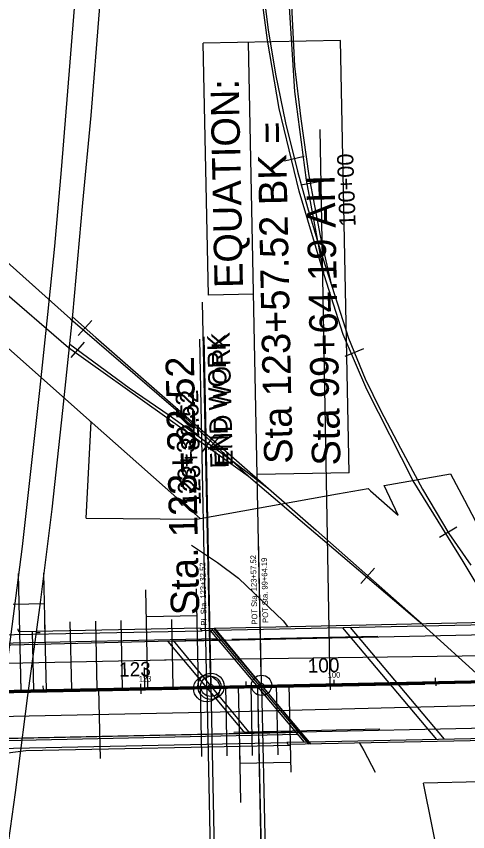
# Model space of a CAD drawing. Extents: x -25029 to 2274964, y -81170 to 687028.
# Drawn here: x -4749.3 to -4526.9, y -66503.3 to -66101.5 of the extents above; entities that cross this region are included whole.
import ezdxf

# ---------------------------------------------------------------- set-up
doc = ezdxf.new("R2010")
doc.units = 0
for name, color, linetype in [('81911BEA - RW_X_Fee_RW', 7, 'Continuous'), ('AP_X_Runway', 7, 'Continuous'), ('BD_X_Canopy', 7, 'Continuous'), ('BR_X_Rail_Object', 7, 'Continuous'), ('Default', 7, 'Continuous'), ('GE_X_CL_100', 7, 'Continuous'), ('GE_X_CL_20', 7, 'Continuous'), ('GK_Visualization', 7, 'Continuous'), ('MT_P_Lane_Line', 7, 'Continuous'), ('PM_P_CL_Double_Solid', 7, 'Continuous'), ('PM_P_Stop_Line', 7, 'Continuous'), ('PV_X_Curb', 7, 'Continuous'), ('PV_X_EOP', 7, 'Continuous'), ('RD_P_Gate', 7, 'Continuous'), ('RD_X_Bumper_Block', 7, 'Continuous'), ('RD_X_GR_Rt', 7, 'Continuous'), ('RD_X_RR_1', 7, 'Continuous'), ('RR', 7, 'Continuous'), ('WALL', 7, 'Continuous')]:
    doc.layers.add(name, color=color, linetype=linetype)

msp = doc.modelspace()

# ---------------------------------------------------------------- linework, layer by layer
at = {"layer": '81911BEA - RW_X_Fee_RW'}
for q in [(-4712.38, -66301.35), (-4660.28, -66349.23)]:
    msp.add_line((-4714.87, -66348.84), q, dxfattribs=at)
for points in [[(-4864.04, -66166.72), (-4711.93, -66301.75), (-4658.75, -66348.95)], [(-4660.28, -66349.23), (-4658.75, -66348.95), (-4591.13, -66336.87), (-4575.99, -66334.17), (-4574.86, -66335.35), (-4561.13, -66347.36), (-4568.02, -66332.74), (-4535.39, -66326.91), (-4528.57, -66339.93), (-4523.13, -66350.33), (-4512.37, -66368.29), (-4506.47, -66378.13), (-4505.97, -66379.3), (-4505.54, -66378.96), (-4505.01, -66378.54), (-4504.45, -66378.09), (-4412.16, -66304.9), (-4388.93, -66286.47), (-4356.73, -66260.93), (-4338.07, -66246.14), (-4326.25, -66236.76), (-4315.27, -66287.59)], [(-4044.67, -66469.26), (-4258.38, -66473.52), (-4520.55, -66478.74), (-4548.73, -66479.3)], [(-4366.67, -67383.31), (-4370, -67366.77), (-4388.22, -67276.31), (-4407.96, -67178.28), (-4459.99, -66919.94), (-4518.67, -66628.59), (-4548.73, -66479.3)]]:
    msp.add_lwpolyline(points, dxfattribs=at)
at = {"layer": 'AP_X_Runway'}
for p, q in [((-3221.39, -66402.05), (-5080.45, -66441.35)), ((-4643.08, -66408.46), (-4571.24, -66406.89)), ((-4655.51, -66432.36), (-4645.53, -66904.41)), ((-4630.51, -66431.83), (-4620.53, -66903.88)), ((-4642.07, -66454.21), (-4570.24, -66452.63))]:
    msp.add_line(p, q, dxfattribs=at)
at = {"layer": 'BD_X_Canopy'}
for p, q in [((-3994.85, -66418.3), (-4628.49, -66431.16)), ((-4817.54, -66435.17), (-4637.91, -66431.34)), ((-4653.48, -66431.67), (-4649.4, -66623.3)), ((-4628.49, -66431.16), (-4624.4, -66622.76))]:
    msp.add_line(p, q, dxfattribs=at)
at = {"layer": 'BR_X_Rail_Object'}
for p, q in [((-4408.27, -66397.98), (-4658.5, -66403.24)), ((-4419.61, -66399.22), (-4651.11, -66404.09)), ((-4657.67, -66404.23), (-4658.5, -66403.24)), ((-4652.39, -66404.11), (-4657.67, -66404.23)), ((-4651.84, -66402.83), (-4604.81, -66459.89)), ((-4542.16, -66457.81), (-4588.48, -66402.77)), ((-4538.31, -66457.73), (-4584.63, -66402.69)), ((-4366.41, -66455.12), (-4615.27, -66460.35)), ((-4374.23, -66454.28), (-4604.78, -66459.13)), ((-4606.07, -66459.15), (-4616.1, -66459.36)), ((-4615.27, -66460.35), (-4616.1, -66459.36))]:
    msp.add_line(p, q, dxfattribs=at)
for points in [[(-4748.36, -66473.6), (-4743.62, -66436.15), (-4737.48, -66391.72), (-4731.64, -66344.36), (-4726.32, -66295.76), (-4721.5, -66248.52), (-4716.56, -66193.33), (-4712.49, -66150.36), (-4708.28, -66098.69), (-4704.66, -66045.85), (-4702.36, -66007), (-4699.76, -65962.58), (-4697.59, -65915.37), (-4695.79, -65870.25), (-4694.24, -65814.53), (-4692.9, -65759.55), (-4692.39, -65727.06)], [(-4705.65, -65739.91), (-4706.22, -65780.42), (-4706.79, -65812.63), (-4708.65, -65857.41), (-4709.97, -65902.73), (-4712.57, -65968.84), (-4714.92, -66010.41), (-4718.38, -66066.51), (-4722.89, -66124.09), (-4727.19, -66177.19), (-4730.56, -66214.73), (-4733.88, -66248.4), (-4737.86, -66285.79), (-4742.36, -66325.83), (-4746.34, -66362.82), (-4748.36, -66378.07)], [(-4748.36, -66378.07), (-4752.9, -66412.35), (-4760.15, -66467.23), (-4766.87, -66514.24), (-4773.38, -66556.56), (-4781.07, -66605.12), (-4786.68, -66637.87), (-4792.77, -66674.62), (-4798.43, -66706.35), (-4805.33, -66743.43), (-4813.25, -66784.09), (-4820.02, -66817.09), (-4826.19, -66846.57), (-4834.14, -66885.13), (-4840.61, -66916.3), (-4850.48, -66960.47), (-4858, -66993.53), (-4866.99, -67033.57), (-4878.63, -67086.62), (-4885.56, -67117.17)], [(-4920.49, -67328.67), (-4909.4, -67280.03), (-4891.96, -67204.02), (-4873.55, -67122.8), (-4856.84, -67045.28), (-4838.99, -66965.27), (-4826.08, -66908.98), (-4815.94, -66860.46), (-4806.52, -66814.99), (-4797.29, -66768.37), (-4788.13, -66721.26), (-4778.55, -66665.39), (-4773.21, -66636.99), (-4767.22, -66601.6), (-4761.9, -66565.78), (-4755.42, -66525.37), (-4749.67, -66483.92), (-4748.36, -66473.6)]]:
    msp.add_lwpolyline(points, dxfattribs=at)
at = {"layer": 'Default'}
for p, q in [((-4594.71, -66430.91), (-4599.66, -66157.23)), ((-4819.56, -66435.63), (-2645.14, -66389.94)), ((-4644.7, -66431.96), (-2645.14, -66389.94)), ((-4607.35, -66459.18), (-4653.68, -66404.14)), ((-4605.24, -66460.14), (-4653.22, -66403.13)), ((-4603.96, -66460.11), (-4651.94, -66403.1)), ((-4648.26, -66409.03), (-4674.54, -66409.58)), ((-4636.48, -66454.79), (-4674.54, -66409.58)), ((-4819.55, -66436.13), (-4021.18, -66419.36)), ((-4594.77, -66428.41), (-4594.66, -66433.41)), ((-4819.56, -66435.63), (-4630.52, -66431.66)), ((-4688.07, -66430.37), (-4687.96, -66435.37)), ((-4630.52, -66431.66), (-4630.52, -66431.66)), ((-4630.52, -66431.66), (-4623.7, -66741.45)), ((-4594.71, -66430.91), (-4594.71, -66430.91)), ((-4688.02, -66432.87), (-4688.02, -66432.87)), ((-4754.17, -66457.26), (-4636.48, -66454.79)), ((-4610.2, -66454.24), (-4636.48, -66454.79))]:
    msp.add_line(p, q, dxfattribs=at)
for points in [[(-4683.02, -66432.76), (-4630.52, -66431.66)], [(-4638.03, -66431.82), (-4630.52, -66431.66)], [(-4630.52, -66431.66), (-4599.71, -66431.01)], [(-4597.21, -66430.96), (-4592.21, -66430.86)], [(-4589.71, -66430.8), (-4544.72, -66429.86)], [(-4544.72, -66429.86), (-4499.73, -66428.91)], [(-4783, -66434.86), (-4738.01, -66433.92)], [(-4738.01, -66433.92), (-4693.02, -66432.97)], [(-4690.52, -66432.92), (-4685.52, -66432.82)]]:
    msp.add_lwpolyline(points, dxfattribs=at)
at = {"layer": 'GE_X_CL_100'}
for p, q in [((-4589.62, -66113.38), (-4657.17, -66114.76)), ((-4654.63, -66238.89), (-4657.17, -66114.76)), ((-4628.59, -66426.16), (-4634.95, -66114.31)), ((-4585.27, -66326.37), (-4589.62, -66113.38)), ((-4632.42, -66238.43), (-4654.63, -66238.89)), ((-4653.59, -66426.68), (-4657.52, -66242.27)), ((-4585.27, -66326.37), (-4630.61, -66327.3)), ((-4686, -66432.37), (-4686.21, -66422.37)), ((-4628.49, -66431.16), (-4371.16, -66425.94)), ((-4817.54, -66435.17), (-4653.48, -66431.67)), ((-4653.48, -66431.67), (-4628.49, -66431.16))]:
    msp.add_line(p, q, dxfattribs=at)
for centre in [(-4653.48, -66431.67), (-4628.49, -66431.16)]:
    msp.add_circle(centre, 5, dxfattribs=at)
at = {"layer": 'GE_X_CL_20'}
for p, q in [((-4659, -66260.53), (-4655.54, -66432.8)), ((-4628.51, -66430.16), (-4629.97, -66358.58)), ((-4653.51, -66430.67), (-4654.99, -66361.14)), ((-4628.51, -66430.16), (-4629.92, -66360.78)), ((-4592.69, -66430.44), (-4592.73, -66428.44)), ((-4542.7, -66429.42), (-4542.74, -66427.42)), ((-5080.45, -66441.35), (-4548.03, -66430.64)), ((-4735.99, -66433.43), (-4736.03, -66431.43)), ((-4686, -66432.37), (-4686.04, -66430.37)), ((-4636.01, -66431.32), (-4636.05, -66429.32)), ((-4542.7, -66429.42), (-4542.66, -66431.42))]:
    msp.add_line(p, q, dxfattribs=at)
for centre, radius in [((-4655.54, -66432.8), 6.46), ((-4653.48, -66431.67), 1), ((-4628.49, -66431.16), 1), ((-4628.49, -66431.16), 1)]:
    msp.add_circle(centre, radius, dxfattribs=at)
at = {"layer": 'GK_Visualization'}
for p, q in [((-4817.54, -66435.17), (-4653.48, -66431.67)), ((-4653.55, -66431.74), (-4653.42, -66431.61)), ((-4653.55, -66431.61), (-4653.42, -66431.74)), ((-4653.48, -66431.67), (-4628.49, -66431.16)), ((-4628.56, -66431.23), (-4628.42, -66431.1)), ((-4628.56, -66431.1), (-4628.42, -66431.23))]:
    msp.add_line(p, q, dxfattribs=at)
at = {"layer": 'MT_P_Lane_Line'}
for p, q in [((-4676.25, -66418.62), (-4292.61, -66413.59)), ((-4640.98, -66444), (-4292.61, -66435.3)), ((-4819.31, -66447.75), (-4640.98, -66444))]:
    msp.add_line(p, q, dxfattribs=at)
msp.add_lwpolyline([(-4816.91, -66421.61), (-4675.49, -66418.59)], dxfattribs=at)
at = {"layer": 'PM_P_CL_Double_Solid'}
for p, q in [((-4628.49, -66431.16), (-4371.16, -66425.94)), ((-4817.54, -66435.17), (-4653.48, -66431.67)), ((-4653.48, -66431.67), (-4628.49, -66431.16))]:
    msp.add_line(p, q, dxfattribs=at)
at = {"layer": 'PM_P_Stop_Line'}
for p, q in [((-4656.9, -66259.35), (-4653.39, -66431.62)), ((-5078.3, -66440.28), (-4545.88, -66429.43))]:
    msp.add_line(p, q, dxfattribs=at)
msp.add_circle((-4653.39, -66431.62), 6.46, dxfattribs=at)
at = {"layer": 'PV_X_Curb'}
for p, q in [((-4759.08, -66410.36), (-4650.37, -66408.07)), ((-4754.67, -66458.28), (-4610.66, -66455.25))]:
    msp.add_line(p, q, dxfattribs=at)
at = {"layer": 'PV_X_EOP'}
for p, q in [((-4775.16, -66406.69), (-4657.67, -66404.23)), ((-4418.74, -66404.21), (-4646.97, -66409)), ((-4759.24, -66411.35), (-4646.47, -66408.53)), ((-4739.12, -66405.13), (-4737.52, -66405.13)), ((-4672.09, -66409.09), (-4634.97, -66454.13)), ((-4380.69, -66449.42), (-4608.92, -66454.21)), ((-4756.17, -66457.36), (-4608.92, -66454.21)), ((-4771.53, -66462.63), (-4616.1, -66459.36))]:
    msp.add_line(p, q, dxfattribs=at)
at = {"layer": 'RD_P_Gate'}
for p, q in [((-4684.49, -66432.34), (-4685.52, -66384.17)), ((-4659.49, -66431.8), (-4660.52, -66383.64)), ((-4734.48, -66433.4), (-4735.19, -66400.07)), ((-4721.98, -66433.13), (-4722.69, -66399.81)), ((-4709.48, -66432.87), (-4710.19, -66399.54)), ((-4696.99, -66432.6), (-4697.7, -66399.27)), ((-4685.24, -66397.3), (-4660.24, -66396.77)), ((-4671.99, -66432.07), (-4672.7, -66398.74)), ((-4746.97, -66433.67), (-4747.58, -66405.11)), ((-4740.73, -66433.53), (-4741.33, -66404.98)), ((-4658.76, -66431.79), (-4658.03, -66466.2)), ((-4646.27, -66431.52), (-4645.53, -66465.93)), ((-4640.02, -66431.39), (-4639.38, -66461.1)), ((-4633.77, -66431.25), (-4633.03, -66465.67)), ((-4621.27, -66430.99), (-4620.54, -66465.4)), ((-4615.02, -66430.85), (-4614.1, -66474)), ((-4708.75, -66432.85), (-4708.02, -66467.27)), ((-4639.38, -66461.1), (-4639.1, -66474.54)), ((-4639.2, -66469.54), (-4614.21, -66469))]:
    msp.add_line(p, q, dxfattribs=at)
at = {"layer": 'RD_X_Bumper_Block'}
for p, q in [((-4747.58, -66405.11), (-4748.19, -66376.12)), ((-4735.09, -66404.85), (-4735.69, -66375.86)), ((-4735.38, -66390.96), (-4750.87, -66391.28)), ((-4746.97, -66434.11), (-4747.58, -66405.11)), ((-4639.38, -66461.1), (-4638.8, -66488.96))]:
    msp.add_line(p, q, dxfattribs=at)
at = {"layer": 'RD_X_GR_Rt'}
for p, q in [((-4658.51, -66402.99), (-4747.59, -66404.86)), ((-4744.63, -66463.32), (-4614.39, -66460.58)), ((-4793.67, -66469.35), (-4744.61, -66463.31))]:
    msp.add_line(p, q, dxfattribs=at)
msp.add_arc((-4746.88, -66403.26), 1.75, 179.2771, 246.3385, dxfattribs=at)
at = {"layer": 'RD_X_RR_1'}
for p, q in [((-4841.97, -66144.32), (-4722.53, -66250.52)), ((-4845.91, -66159.43), (-4723.54, -66264.71)), ((-4634.87, -66328.15), (-4550.85, -66399.64)), ((-4550.85, -66399.64), (-4487.02, -66457.75))]:
    msp.add_line(p, q, dxfattribs=at)
for points in [[(-4597.6, -66228.85), (-4609.92, -66187.68), (-4619.75, -66146.86), (-4625.59, -66113.26), (-4630.21, -66078.5), (-4632.55, -66033.6), (-4633.23, -65990.83), (-4631.36, -65944.3), (-4627.34, -65906.82), (-4620.62, -65868.34), (-4610.48, -65826.46), (-4597.2, -65784.59), (-4582.75, -65745.62), (-4571.86, -65719.84), (-4564.39, -65699.83)], [(-4597.6, -66228.85), (-4606.28, -66182.22), (-4612.14, -66138.57), (-4614.9, -66094.36), (-4616.6, -66053.06), (-4617.05, -65999.36), (-4614.9, -65976.3), (-4608.89, -65937.71), (-4601.28, -65907.39), (-4590.62, -65877.45), (-4572.61, -65833.41), (-4556.8, -65796.43)], [(-4511.35, -66399.76), (-4529.14, -66370.19), (-4553.86, -66330.34), (-4576.69, -66285.41), (-4588.24, -66258.35), (-4597.6, -66228.85)], [(-4722.53, -66250.52), (-4665.88, -66299.4), (-4634.87, -66328.15)], [(-4723.54, -66264.71), (-4677.46, -66297.58), (-4634.87, -66328.15)]]:
    msp.add_lwpolyline(points, dxfattribs=at)
at = {"layer": 'RR'}
for p, q in [((-4617.2, -66172.76), (-4607.48, -66170.39)), ((-4599.37, -66182.88), (-4609.2, -66184.74)), ((-4718.76, -66258.8), (-4712.13, -66251.31)), ((-4722.27, -66269.59), (-4715.67, -66262.08)), ((-4587.36, -66268.92), (-4578.1, -66265.16)), ((-4657.6, -66316.08), (-4651.75, -66307.97)), ((-4654.62, -66314.93), (-4648.04, -66307.41)), ((-4540.84, -66358.18), (-4532.26, -66353.05)), ((-4579.52, -66380.91), (-4572.89, -66373.42))]:
    msp.add_line(p, q, dxfattribs=at)
for points in [[(-4594.2, -66232.77), (-4599.41, -66209.71), (-4604.99, -66180.05), (-4608.97, -66151.91), (-4612.03, -66125.96), (-4613.32, -66099.43), (-4614.36, -66079.36), (-4614.76, -66056.98), (-4615.13, -66032.91), (-4615.77, -66017.13), (-4615.14, -65999.12), (-4614.65, -65984.92), (-4613.02, -65967.61), (-4610.69, -65953.78), (-4608.01, -65938.73), (-4602.88, -65919.16), (-4595.41, -65894.06), (-4583.34, -65861.2), (-4569, -65826.76), (-4536.45, -65749.56)], [(-4627.58, -66089.69), (-4625.21, -66108.15), (-4621.68, -66129.96), (-4616.62, -66154.04), (-4610.81, -66177.85), (-4605.85, -66195.67), (-4599.71, -66216.03), (-4592.59, -66238.51), (-4585.58, -66260.03), (-4577.4, -66280.15), (-4569.89, -66295.5), (-4559.98, -66314.21), (-4549.22, -66334.43), (-4536.17, -66356.26), (-4525.4, -66371.93)], [(-4721.61, -66249.56), (-4710.12, -66259.71), (-4601.61, -66354.69), (-4549.39, -66400.9)], [(-4722.98, -66262.96), (-4693.72, -66284.51), (-4674.01, -66298.08), (-4642.01, -66321.15), (-4624.82, -66334.34)]]:
    msp.add_lwpolyline(points, dxfattribs=at)
at = {"layer": 'WALL'}
for points in [[(-4663.05, -66362.02), (-4650.13, -66370.65), (-4639.85, -66378.43), (-4628.4, -66389.28), (-4617.75, -66399.44), (-4615.64, -66402.14)], [(-4580.31, -66459.4), (-4578.02, -66463.22), (-4572.55, -66473.98)]]:
    msp.add_lwpolyline(points, dxfattribs=at)

# ---------------------------------------------------------------- texts
at = {"layer": 'Default'}
for s, height, rotation, p in [('100+00', 8, 91.9961, (-4582.1, -66204.95)), ('123', 7, 1.2038, (-4698.61, -66426.9)), ('100', 7, 1.2038, (-4605.66, -66424.95))]:
    msp.add_text(s, height=height, rotation=rotation, dxfattribs=at).set_placement(p)
at = {"layer": 'GE_X_CL_100'}
for s, rotation, p in [('EQUATION:', 91.1689, (-4637.62, -66235.23)), ('Sta 123+57.52 BK = ', 91.1689, (-4613.16, -66321.86)), ('Sta 99+64.19 AH', 91.1689, (-4589.59, -66322.74)), ('Sta. 123+32.52', 91.2216, (-4659.11, -66396.44))]:
    msp.add_text(s, height=14, rotation=rotation, dxfattribs=at).set_placement(p)
at = {"layer": 'GE_X_CL_20'}
for s, height, rotation, p in [('END WORK', 8.96, 91.4394, (-4644.7, -66324.1)), ('123+32.52', 8.96, 91.4394, (-4660.45, -66343.53)), ('POT Sta. 123+57.52', 2.8, 91.1689, (-4630.5, -66401.2)), ('POT Sta. 99+64.19', 2.8, 91.1627, (-4625.16, -66400.38)), ('PI  Sta. 123+32.52', 2.8, 91.2216, (-4655.52, -66401.71)), ('100', 2.8, 1.1627, (-4595.87, -66427.5)), ('123', 2.8, 1.2216, (-4688.99, -66429.43))]:
    msp.add_text(s, height=height, rotation=rotation, dxfattribs=at).set_placement(p)
at = {"layer": 'GK_Visualization'}
for s, p in [('48', (-4653.48, -66431.67)), ('49', (-4628.49, -66431.16))]:
    msp.add_text(s, height=0.14, dxfattribs=at).set_placement(p)
at = {"layer": 'PM_P_Stop_Line'}
for s, p in [('END WORK', (-4642.58, -66322.92)), ('123+32.52', (-4658.32, -66342.35))]:
    msp.add_text(s, height=8.96, rotation=91.4541, dxfattribs=at).set_placement(p)

doc.saveas('drawing.dxf')
